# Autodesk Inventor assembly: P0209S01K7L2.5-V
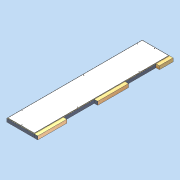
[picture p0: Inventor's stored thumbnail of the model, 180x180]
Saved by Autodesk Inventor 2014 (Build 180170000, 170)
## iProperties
Justset: False
Created: 2011-04
Part Number: P0209S01K7L2.5-V
Document SubType Name: Assembly
Designer: david.appleford
Description: 0.5w x 2.25w 01 Panel - 7 Locks 2.5 Lugs
Mass: 28000 g
Surface Area: 38413 cm^2
Volume: 122014 cm^3
Density: 0.229481 g/cm^3
Cost Center: £113.00
Title: 0.5w x 2.25w 01 Panel - 7 Locks 2.5 Lugs
Author: david.appleford
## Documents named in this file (5)
- C:\Documents and Settings\john.everitt\Local Settings\My Documents\Vault\Production MkII\VIRTUAL ELEMENTS\Virtual Walls\Virtual Timber + MgO\P0209S01K7L2.5-V.iam
- C:\Documents and Settings\john.everitt\Local Settings\My Documents\Vault\Production MkII\VIRTUAL ELEMENTS\Virtual Lugs\Superceded Lugs\LA02C3V.ipt
- C:\Documents and Settings\john.everitt\Local Settings\My Documents\Vault\Production MkII\VIRTUAL ELEMENTS\Virtual Lugs\Superceded Lugs\LA02M3V.ipt
- C:\Documents and Settings\john.everitt\Local Settings\My Documents\Vault\Production MkII\Virtual Elements\Virtual Walls\Virtual Timber + MgO\P0209S01K7-V.ipt
- C:\Documents and Settings\john.everitt\Local Settings\My Documents\Vault\Production MkII\VIRTUAL ELEMENTS\Virtual Lugs\Superceded Lugs\LA01C3V.ipt
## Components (4 placed, 4 different names)
1. P0209S01K7-V:1 — Mate:1, Flush:1, Flush:2, Mate:7, Flush:11, Mate:15, Flush:14, Flush:15
2. LA02C3V:1 — Mate:1, Flush:1, Flush:2, Mate:9
3. LA02M3V:4 — Mate:7, Flush:11, Mate:9
4. LA01C3V:1 — Mate:15, Flush:14, Flush:15
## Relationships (9: Flush 5, Mate 4)
- Mate:1: P0209S01K7-V:1 ↔ LA02C3V:1
- Flush:1: P0209S01K7-V:1 ↔ LA02C3V:1
- Flush:2: P0209S01K7-V:1 ↔ LA02C3V:1
- Mate:7: P0209S01K7-V:1 ↔ LA02M3V:4
- Flush:11: P0209S01K7-V:1 ↔ LA02M3V:4
- Mate:9: LA02C3V:1 ↔ LA02M3V:4
- Mate:15: P0209S01K7-V:1 ↔ LA01C3V:1
- Flush:14: P0209S01K7-V:1 ↔ LA01C3V:1
- Flush:15: P0209S01K7-V:1 ↔ LA01C3V:1
## Named parameters: t = 1 mm, Cl = 2 mm
